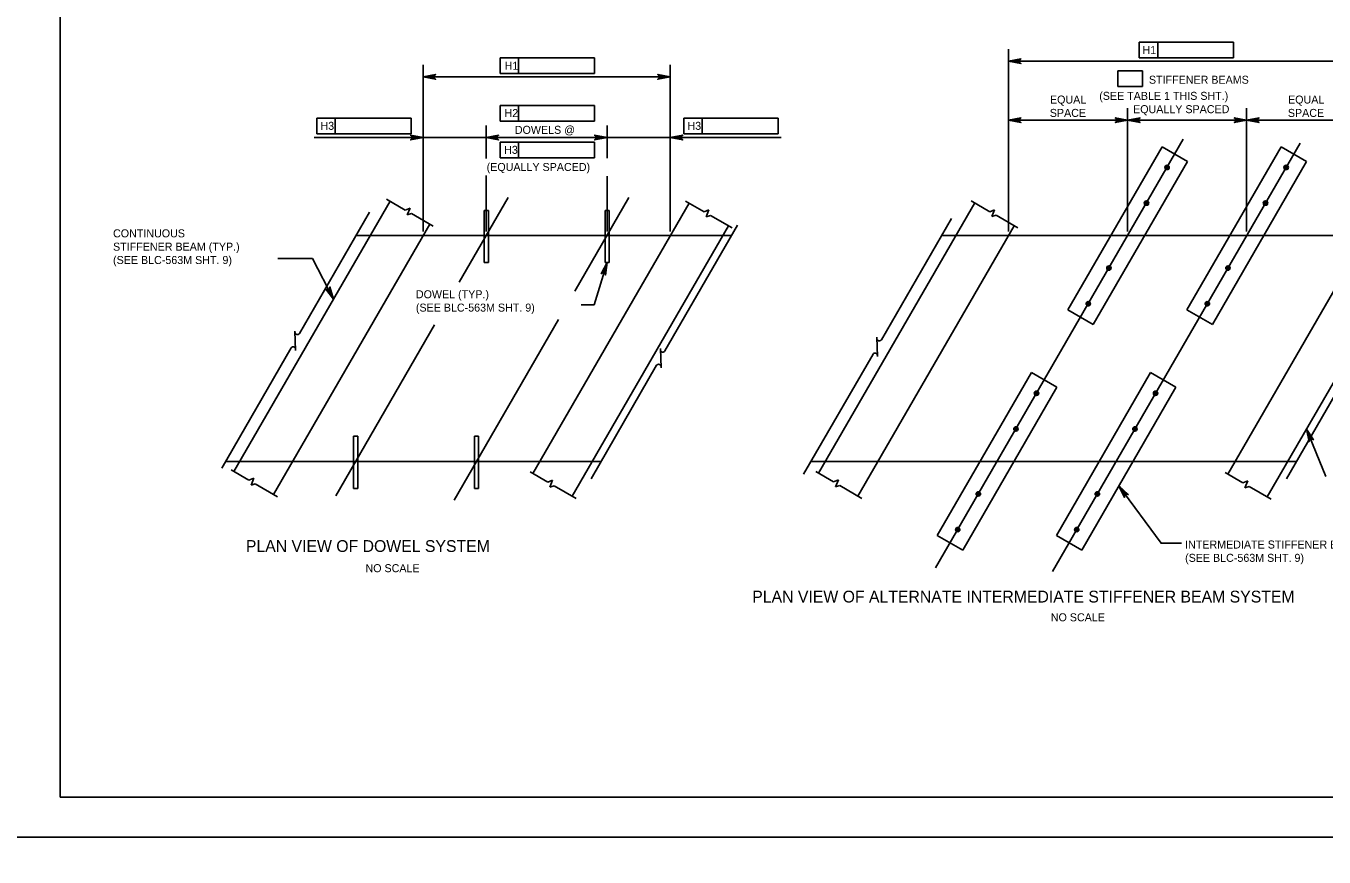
# Model space of a CAD drawing. Extents: x 638268 to 640277, y 295465 to 298435.
# Drawn here: x 639303.6 to 639790.3, y 297834 to 298145.6 of the extents above; entities that cross this region are included whole.
import ezdxf

# ---------------------------------------------------------------- set-up
doc = ezdxf.new("R2010")
doc.units = 0
for name, color, linetype in [('2', 7, 'Continuous'), ('3', 7, 'Continuous'), ('4', 7, 'Continuous'), ('PLT-BNDY', 7, 'Continuous')]:
    doc.layers.add(name, color=color, linetype=linetype)

# ---------------------------------------------------------------- blocks, each defined once
blk = doc.blocks.new('D')
at = {"layer": '3'}
for p, q in [((-0.48575, 0.574125), (-0.574125, 0.48575)), ((0.52325, -0.6115), (-0.574125, 0.48575)), ((0.6115, -0.52325), (-0.48575, 0.574125)), ((0.6115, -0.52325), (0.52325, -0.6115))]:
    blk.add_line(p, q, dxfattribs=at)

msp = doc.modelspace()

# ---------------------------------------------------------------- linework, layer by layer
at = {"layer": '2'}
for p, q in [((639316.46, 297856.46), (639316.46, 298420.46)), ((639427.37, 298067.04), (639568.2, 298067.04)), ((639646.92, 298067.04), (639828.98, 298067.04)), ((639378.41, 297982.34), (639519.24, 297982.34)), ((639597.96, 297982.34), (639780.02, 297982.34)), ((640102.46, 297856.46), (639316.46, 297856.46))]:
    msp.add_line(p, q, dxfattribs=at)
at = {"layer": '3'}
for p, q in [((639729.59, 298100.33), (639694.27, 298039.24)), ((639729.59, 298100.33), (639739.14, 298094.82)), ((639774.23, 298100.33), (639738.91, 298039.24)), ((639774.23, 298100.33), (639783.77, 298094.82)), ((639739.14, 298094.82), (639703.82, 298033.72)), ((639783.77, 298094.82), (639748.45, 298033.72)), ((639440.13, 298079.89), (639381.55, 297978.53)), ((639445.79, 298076.62), (639438.78, 298080.67)), ((639466.08, 298049.6), (639484.38, 298081.27)), ((639552.21, 298079.22), (639493.62, 297977.86)), ((639509.42, 298046.17), (639529.69, 298081.27)), ((639557.87, 298075.95), (639550.86, 298080)), ((639659.34, 298079.28), (639600.75, 297977.92)), ((639665, 298076), (639657.98, 298080.06)), ((639812.83, 298078.94), (639754.24, 297977.59)), ((639432.43, 298075.81), (639406.14, 298030.32)), ((639447.59, 298077.36), (639445.79, 298076.62)), ((639446.58, 298074.76), (639447.59, 298077.36)), ((639448.13, 298075.27), (639446.58, 298074.76)), ((639456.29, 298070.55), (639448.13, 298075.27)), ((639559.67, 298076.68), (639557.87, 298075.95)), ((639558.66, 298074.08), (639559.67, 298076.68)), ((639560.21, 298074.59), (639558.66, 298074.08)), ((639568.37, 298069.88), (639560.21, 298074.59)), ((639666.8, 298076.74), (639665, 298076)), ((639665.78, 298074.14), (639666.8, 298076.74)), ((639667.34, 298074.65), (639665.78, 298074.14)), ((639675.5, 298069.93), (639667.34, 298074.65)), ((639396.37, 297969.96), (639454.96, 298071.32)), ((639508.45, 297969.29), (639567.04, 298070.65)), ((639570.45, 298070.93), (639543.18, 298023.76)), ((639615.57, 297969.35), (639674.16, 298070.71)), ((639650.63, 298073.47), (639624.34, 298027.98)), ((639769.07, 297969.02), (639827.65, 298070.37)), ((639476.96, 298067.04), (639475.39, 298067.04)), ((639522.28, 298067.04), (639520.71, 298067.04)), ((639464.14, 297967.81), (639503.3, 298035.58)), ((639694.27, 298039.24), (639703.82, 298033.72)), ((639738.91, 298039.24), (639748.45, 298033.72)), ((639404.43, 298031.23), (639404.7, 298023.96)), ((639419.72, 297969.37), (639456.83, 298033.59)), ((639622.63, 298028.89), (639622.9, 298021.62)), ((639403.03, 298024.94), (639376.97, 297979.86)), ((639541.47, 298024.67), (639541.74, 298017.4)), ((639621.23, 298022.6), (639595.17, 297977.52)), ((639540.07, 298018.38), (639515.48, 297975.83)), ((639680.63, 298015.63), (639645.31, 297954.53)), ((639680.63, 298015.63), (639690.17, 298010.12)), ((639725.27, 298015.63), (639689.95, 297954.53)), ((639725.27, 298015.63), (639734.81, 298010.12)), ((639800.85, 298018.38), (639776.26, 297975.83)), ((639690.17, 298010.12), (639654.86, 297949.02)), ((639734.81, 298010.12), (639699.49, 297949.02)), ((639387.2, 297975.26), (639380.52, 297979.13)), ((639499.28, 297974.59), (639492.6, 297978.45)), ((639606.41, 297974.65), (639599.72, 297978.51)), ((639759.9, 297974.32), (639753.21, 297978.18)), ((639389, 297976), (639387.2, 297975.26)), ((639387.99, 297973.4), (639389, 297976)), ((639389.55, 297973.91), (639387.99, 297973.4)), ((639397.87, 297969.1), (639389.55, 297973.91)), ((639501.08, 297975.33), (639499.28, 297974.59)), ((639500.07, 297972.73), (639501.08, 297975.33)), ((639501.63, 297973.23), (639500.07, 297972.73)), ((639509.95, 297968.42), (639501.63, 297973.23)), ((639608.21, 297975.38), (639606.41, 297974.65)), ((639607.19, 297972.78), (639608.21, 297975.38)), ((639608.75, 297973.29), (639607.19, 297972.78)), ((639617.07, 297968.48), (639608.75, 297973.29)), ((639761.7, 297975.05), (639759.9, 297974.32)), ((639760.69, 297972.45), (639761.7, 297975.05)), ((639762.24, 297972.96), (639760.69, 297972.45)), ((639770.56, 297968.15), (639762.24, 297972.96)), ((639645.31, 297954.53), (639654.86, 297949.02)), ((639689.95, 297954.53), (639699.49, 297949.02))]:
    msp.add_line(p, q, dxfattribs=at)
for centre, radius in [((639731.48, 298092.59), 0.833), ((639731.48, 298092.59), 0.738), ((639731.48, 298092.59), 0.625), ((639776.12, 298092.59), 0.833), ((639776.12, 298092.59), 0.738), ((639776.12, 298092.59), 0.625), ((639731.48, 298092.59), 0.417), ((639731.48, 298092.59), 0.208), ((639776.12, 298092.59), 0.417), ((639776.12, 298092.59), 0.208), ((639723.75, 298079.21), 0.833), ((639723.75, 298079.21), 0.738), ((639723.75, 298079.21), 0.625), ((639723.75, 298079.21), 0.417), ((639723.75, 298079.21), 0.208), ((639768.38, 298079.21), 0.833), ((639768.38, 298079.21), 0.738), ((639768.38, 298079.21), 0.625), ((639768.38, 298079.21), 0.417), ((639768.38, 298079.21), 0.208), ((639709.66, 298054.84), 0.833), ((639709.66, 298054.84), 0.738), ((639709.66, 298054.84), 0.625), ((639709.66, 298054.84), 0.417), ((639709.66, 298054.84), 0.208), ((639754.3, 298054.84), 0.833), ((639754.3, 298054.84), 0.738), ((639754.3, 298054.84), 0.625), ((639754.3, 298054.84), 0.417), ((639754.3, 298054.84), 0.208), ((639701.93, 298041.47), 0.833), ((639701.93, 298041.47), 0.738), ((639701.93, 298041.47), 0.625), ((639701.93, 298041.47), 0.417), ((639701.93, 298041.47), 0.208), ((639746.56, 298041.47), 0.833), ((639746.56, 298041.47), 0.738), ((639746.56, 298041.47), 0.625), ((639746.56, 298041.47), 0.417), ((639746.56, 298041.47), 0.208), ((639682.52, 298007.89), 0.833), ((639682.52, 298007.89), 0.738), ((639682.52, 298007.89), 0.625), ((639682.52, 298007.89), 0.417), ((639682.52, 298007.89), 0.208), ((639727.16, 298007.89), 0.833), ((639727.16, 298007.89), 0.738), ((639727.16, 298007.89), 0.625), ((639727.16, 298007.89), 0.417), ((639727.16, 298007.89), 0.208), ((639674.79, 297994.51), 0.833), ((639674.79, 297994.51), 0.738), ((639674.79, 297994.51), 0.625), ((639674.79, 297994.51), 0.417), ((639674.79, 297994.51), 0.208), ((639719.42, 297994.51), 0.833), ((639719.42, 297994.51), 0.738), ((639719.42, 297994.51), 0.625), ((639719.42, 297994.51), 0.417), ((639719.42, 297994.51), 0.208), ((639660.7, 297970.14), 0.833), ((639660.7, 297970.14), 0.738), ((639660.7, 297970.14), 0.625), ((639660.7, 297970.14), 0.417), ((639660.7, 297970.14), 0.208), ((639705.34, 297970.14), 0.833), ((639705.34, 297970.14), 0.738), ((639705.34, 297970.14), 0.625), ((639705.34, 297970.14), 0.417), ((639705.34, 297970.14), 0.208), ((639652.97, 297956.76), 0.833), ((639652.97, 297956.76), 0.738), ((639652.97, 297956.76), 0.625), ((639652.97, 297956.76), 0.417), ((639652.97, 297956.76), 0.208), ((639697.6, 297956.76), 0.833), ((639697.6, 297956.76), 0.738), ((639697.6, 297956.76), 0.625), ((639697.6, 297956.76), 0.417), ((639697.6, 297956.76), 0.208)]:
    msp.add_circle(centre, radius, dxfattribs=at)
for centre, start, end in [((639405.36, 298030.78), 179.9708, 329.9708), ((639403.77, 298024.42), 2.1036, 144.6422), ((639623.55, 298028.44), 179.9708, 329.9708), ((639542.4, 298024.22), 179.9708, 329.9708), ((639621.97, 298022.08), 2.1036, 144.6422), ((639540.82, 298017.86), 2.1036, 144.6422)]:
    msp.add_arc(centre, 0.909, start, end, dxfattribs=at)
at = {"layer": '4'}
for p, q in [((639721.06, 298139.63), (639721.06, 298133.73)), ((639721.06, 298139.63), (639756.36, 298139.63)), ((639727.95, 298139.63), (639727.95, 298133.73)), ((639756.36, 298139.63), (639756.36, 298133.73)), ((639481.44, 298133.75), (639516.74, 298133.75)), ((639481.44, 298133.75), (639481.44, 298127.84)), ((639488.33, 298133.75), (639488.33, 298127.84)), ((639516.74, 298133.75), (639516.74, 298127.84)), ((639672.04, 298068.61), (639672.04, 298136.91)), ((639805.95, 298132.41), (639672.04, 298132.41)), ((639756.36, 298133.73), (639721.06, 298133.73)), ((639452.48, 298070.17), (639452.48, 298131.02)), ((639516.74, 298127.84), (639481.44, 298127.84)), ((639545.17, 298070.17), (639545.17, 298131.02)), ((639712.97, 298128.8), (639722.25, 298128.8)), ((639712.97, 298128.8), (639712.97, 298122.89)), ((639722.25, 298128.8), (639722.25, 298122.89)), ((639545.17, 298126.52), (639452.48, 298126.52)), ((639722.25, 298122.89), (639712.97, 298122.89)), ((639481.44, 298115.88), (639481.44, 298109.97)), ((639481.44, 298115.88), (639516.74, 298115.88)), ((639488.33, 298115.88), (639488.33, 298109.97)), ((639516.74, 298115.88), (639516.74, 298109.97)), ((639672.04, 298068.61), (639672.04, 298114.76)), ((639716.68, 298068.61), (639716.68, 298114.76)), ((639761.31, 298068.61), (639761.31, 298114.76)), ((639412.67, 298111.08), (639447.97, 298111.08)), ((639412.67, 298111.08), (639412.67, 298105.18)), ((639419.56, 298111.08), (639419.56, 298105.18)), ((639447.97, 298111.08), (639447.97, 298105.18)), ((639452.48, 298068.61), (639452.48, 298108.32)), ((639476.16, 298095.9), (639476.16, 298108.32)), ((639516.74, 298109.97), (639481.44, 298109.97)), ((639521.48, 298096.09), (639521.48, 298108.32)), ((639545.17, 298068.61), (639545.17, 298108.32)), ((639550.3, 298111.08), (639585.6, 298111.08)), ((639550.3, 298111.08), (639550.3, 298105.18)), ((639557.19, 298111.08), (639557.19, 298105.18)), ((639585.6, 298111.08), (639585.6, 298105.18)), ((639713.68, 298110.26), (639672.04, 298110.26)), ((639758.31, 298110.26), (639719.68, 298110.26)), ((639764.31, 298110.26), (639805.95, 298110.26)), ((639449.48, 298103.82), (639411.6, 298103.82)), ((639447.97, 298105.18), (639412.67, 298105.18)), ((639476.16, 298103.82), (639452.46, 298103.82)), ((639518.47, 298103.82), (639479.16, 298103.82)), ((639518.47, 298103.82), (639515.47, 298103.82)), ((639545.17, 298103.82), (639521.47, 298103.82)), ((639548.17, 298103.82), (639586.76, 298103.82)), ((639585.6, 298105.18), (639550.3, 298105.18)), ((639737.54, 298103.13), (639644.64, 297942.41)), ((639481.44, 298102.09), (639516.74, 298102.09)), ((639481.44, 298102.09), (639481.44, 298096.19)), ((639488.33, 298102.09), (639488.33, 298096.19)), ((639516.74, 298102.09), (639516.74, 298096.19)), ((639781.36, 298101.73), (639688.46, 297941.01)), ((639516.74, 298096.19), (639481.44, 298096.19)), ((639476.16, 298068.61), (639476.16, 298089.57)), ((639521.48, 298068.61), (639521.48, 298089.27)), ((639411.07, 298058.42), (639397.98, 298058.42)), ((639516.63, 298041.04), (639511.77, 298041.04)), ((639729.1, 297951.66), (639736.94, 297951.66))]:
    msp.add_line(p, q, dxfattribs=at)
for points in [[(639672.04, 298132.41), (639676.7, 298133.28), (639676.35, 298133.03), (639676.16, 298132.72), (639676.11, 298132.41), (639676.16, 298132.09), (639676.35, 298131.78), (639676.7, 298131.53), (639672.04, 298132.41), (639676.35, 298131.78), (639676.16, 298132.09), (639672.04, 298132.41), (639676.11, 298132.41), (639676.16, 298132.72), (639672.04, 298132.41), (639676.35, 298133.03)], [(639452.48, 298126.52), (639457.15, 298127.39), (639456.79, 298127.15), (639456.6, 298126.83), (639456.55, 298126.52), (639456.6, 298126.21), (639456.79, 298125.9), (639457.15, 298125.65), (639452.48, 298126.52), (639456.79, 298125.9), (639456.6, 298126.21), (639452.48, 298126.52), (639456.55, 298126.52), (639456.6, 298126.83), (639452.48, 298126.52), (639456.79, 298127.15)], [(639545.17, 298126.52), (639540.51, 298125.65), (639540.87, 298125.9), (639541.06, 298126.21), (639541.11, 298126.52), (639541.06, 298126.83), (639540.87, 298127.15), (639540.51, 298127.39), (639545.17, 298126.52), (639540.87, 298127.15), (639541.06, 298126.83), (639545.17, 298126.52), (639541.11, 298126.52), (639541.06, 298126.21), (639545.17, 298126.52), (639540.87, 298125.9)], [(639672.04, 298110.26), (639676.7, 298111.13), (639676.35, 298110.88), (639676.16, 298110.57), (639676.11, 298110.26), (639676.16, 298109.94), (639676.35, 298109.63), (639676.7, 298109.38), (639672.04, 298110.26), (639676.35, 298109.63), (639676.16, 298109.94), (639672.04, 298110.26), (639676.11, 298110.26), (639676.16, 298110.57), (639672.04, 298110.26), (639676.35, 298110.88)], [(639716.68, 298110.26), (639712.02, 298109.38), (639712.38, 298109.63), (639712.56, 298109.94), (639712.62, 298110.26), (639712.56, 298110.57), (639712.38, 298110.88), (639712.02, 298111.13), (639716.68, 298110.26), (639712.38, 298110.88), (639712.56, 298110.57), (639716.68, 298110.26), (639712.62, 298110.26), (639712.56, 298109.94), (639716.68, 298110.26), (639712.38, 298109.63)], [(639716.68, 298110.26), (639721.34, 298109.38), (639720.98, 298109.63), (639720.8, 298109.94), (639720.74, 298110.26), (639720.8, 298110.57), (639720.98, 298110.88), (639721.34, 298111.13), (639716.68, 298110.26), (639720.98, 298110.88), (639720.8, 298110.57), (639716.68, 298110.26), (639720.74, 298110.26), (639720.8, 298109.94), (639716.68, 298110.26), (639720.98, 298109.63)], [(639761.31, 298110.26), (639756.65, 298109.38), (639757.01, 298109.63), (639757.2, 298109.94), (639757.25, 298110.26), (639757.2, 298110.57), (639757.01, 298110.88), (639756.65, 298111.13), (639761.31, 298110.26), (639757.01, 298110.88), (639757.2, 298110.57), (639761.31, 298110.26), (639757.25, 298110.26), (639757.2, 298109.94), (639761.31, 298110.26), (639757.01, 298109.63)], [(639761.31, 298110.26), (639765.98, 298109.38), (639765.62, 298109.63), (639765.43, 298109.94), (639765.38, 298110.26), (639765.43, 298110.57), (639765.62, 298110.88), (639765.98, 298111.13), (639761.31, 298110.26), (639765.62, 298110.88), (639765.43, 298110.57), (639761.31, 298110.26), (639765.38, 298110.26), (639765.43, 298109.94), (639761.31, 298110.26), (639765.62, 298109.63)], [(639452.48, 298103.82), (639447.82, 298102.94), (639448.18, 298103.19), (639448.37, 298103.5), (639448.42, 298103.82), (639448.37, 298104.13), (639448.18, 298104.44), (639447.82, 298104.69), (639452.48, 298103.82), (639448.18, 298104.44), (639448.37, 298104.13), (639452.48, 298103.82), (639448.42, 298103.82), (639448.37, 298103.5), (639452.48, 298103.82), (639448.18, 298103.19)], [(639476.16, 298103.82), (639480.82, 298104.69), (639480.46, 298104.44), (639480.27, 298104.13), (639480.22, 298103.82), (639480.27, 298103.5), (639480.46, 298103.19), (639480.82, 298102.94), (639476.16, 298103.82), (639480.46, 298103.19), (639480.27, 298103.5), (639476.16, 298103.82), (639480.22, 298103.82), (639480.27, 298104.13), (639476.16, 298103.82), (639480.46, 298104.44)], [(639521.47, 298103.82), (639516.81, 298102.94), (639517.17, 298103.19), (639517.36, 298103.5), (639517.41, 298103.82), (639517.36, 298104.13), (639517.17, 298104.44), (639516.81, 298104.69), (639521.47, 298103.82), (639517.17, 298104.44), (639517.36, 298104.13), (639521.47, 298103.82), (639517.41, 298103.82), (639517.36, 298103.5), (639521.47, 298103.82), (639517.17, 298103.19)], [(639545.17, 298103.82), (639549.84, 298104.69), (639549.48, 298104.44), (639549.29, 298104.13), (639549.24, 298103.82), (639549.29, 298103.5), (639549.48, 298103.19), (639549.84, 298102.94), (639545.17, 298103.82), (639549.48, 298103.19), (639549.29, 298103.5), (639545.17, 298103.82), (639549.24, 298103.82), (639549.29, 298104.13), (639545.17, 298103.82), (639549.48, 298104.44)], [(639418.95, 298043.24), (639411.07, 298058.42)], [(639521.48, 298056.93), (639516.62, 298041.03)], [(639521.48, 298056.93), (639520.95, 298052.22), (639520.82, 298052.64), (639520.58, 298052.91), (639520.29, 298053.05), (639519.98, 298053.09), (639519.62, 298053), (639519.28, 298052.73), (639521.48, 298056.93), (639519.62, 298053), (639519.98, 298053.09), (639521.48, 298056.93), (639520.29, 298053.05), (639520.58, 298052.91), (639521.48, 298056.93), (639520.82, 298052.64)], [(639418.95, 298043.24), (639416.02, 298046.97), (639416.41, 298046.77), (639416.77, 298046.75), (639417.08, 298046.85), (639417.33, 298047.04), (639417.52, 298047.35), (639417.58, 298047.78), (639418.95, 298043.24), (639417.52, 298047.35), (639417.33, 298047.04), (639418.95, 298043.24), (639417.08, 298046.85), (639416.77, 298046.75), (639418.95, 298043.24), (639416.41, 298046.77)], [(639783.76, 297994.44), (639790.99, 297976.71)], [(639783.76, 297994.44), (639786.33, 297990.45), (639785.96, 297990.69), (639785.6, 297990.74), (639785.3, 297990.67), (639785.03, 297990.51), (639784.81, 297990.22), (639784.71, 297989.79), (639783.76, 297994.44), (639784.81, 297990.22), (639785.03, 297990.51), (639783.76, 297994.44), (639785.3, 297990.67), (639785.6, 297990.74), (639783.76, 297994.44), (639785.96, 297990.69)], [(639713.43, 297973.12), (639729.2, 297951.63)], [(639713.43, 297973.12), (639716.89, 297969.88), (639716.47, 297970.02), (639716.11, 297969.99), (639715.83, 297969.85), (639715.61, 297969.62), (639715.47, 297969.28), (639715.48, 297968.85), (639713.43, 297973.12), (639715.47, 297969.28), (639715.61, 297969.62), (639713.43, 297973.12), (639715.83, 297969.85), (639716.11, 297969.99), (639713.43, 297973.12), (639716.47, 297970.02)]]:
    msp.add_lwpolyline(points, dxfattribs=at)
for points in [[(639675.04, 298132.91), (639675.04, 298131.91), (639672.04, 298132.41)], [(639455.48, 298127.02), (639455.48, 298126.02), (639452.48, 298126.52)], [(639542.17, 298127.02), (639542.17, 298126.02), (639545.17, 298126.52)], [(639675.04, 298110.76), (639675.04, 298109.76), (639672.04, 298110.26)], [(639713.68, 298110.76), (639713.68, 298109.76), (639716.68, 298110.26)], [(639719.68, 298110.76), (639719.68, 298109.76), (639716.68, 298110.26)], [(639758.31, 298110.76), (639758.31, 298109.76), (639761.31, 298110.26)], [(639764.31, 298110.76), (639764.31, 298109.76), (639761.31, 298110.26)], [(639449.48, 298104.32), (639449.48, 298103.32), (639452.48, 298103.82)], [(639479.16, 298104.32), (639479.16, 298103.32), (639476.16, 298103.82)], [(639518.47, 298104.32), (639518.47, 298103.32), (639521.47, 298103.82)], [(639548.17, 298104.32), (639548.17, 298103.32), (639545.17, 298103.82)], [(639521.48, 298056.93), (639520.36, 298054.14), (639520.84, 298053.99)], [(639418.95, 298043.24), (639417.79, 298046.02), (639417.34, 298045.79)], [(639783.76, 297994.44), (639784.66, 297991.57), (639785.13, 297991.75)], [(639713.43, 297973.12), (639715, 297970.56), (639715.4, 297970.85)]]:
    msp.add_lwpolyline(points, close=True, dxfattribs=at)
at = {"layer": 'PLT-BNDY'}
for points in [[(639276.46, 298435.46), (640117.46, 298435.46), (640117.46, 297841.46), (639276.46, 297841.46)], [(639276.46, 297841.46), (640117.46, 297841.46), (640117.46, 297247.46), (639276.46, 297247.46)]]:
    msp.add_lwpolyline(points, close=True, dxfattribs=at)

# ---------------------------------------------------------------- block references
at = {"layer": '4', "xscale": 12.59905511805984, "yscale": -12.599055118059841, "rotation": -135.00004849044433}
for p in [(639476.18, 298067.04), (639521.5, 298067.04), (639427.22, 297982.34), (639472.54, 297982.34)]:
    msp.add_blockref('D', p, dxfattribs=at)

# ---------------------------------------------------------------- texts
at = {"layer": '4'}
for s, height, p in [('H1', 3, (639722.24, 298135.09)), ('H1', 3, (639483.07, 298129.21)), ('STIFFENER BEAMS', 3, (639724.67, 298123.98)), ('EQUAL', 3, (639687.57, 298116.54)), ('(SEE TABLE 1 THIS SHT.)', 3, (639706.04, 298117.94)), ('EQUAL', 3, (639776.84, 298116.54)), ('H2', 3, (639483.03, 298111.47)), ('SPACE', 3, (639687.5, 298111.54)), ('EQUALLY SPACED', 3, (639718.73, 298112.94)), ('SPACE', 3, (639776.77, 298111.54)), ('H3', 3, (639414, 298106.69)), ('DOWELS @', 3, (639486.9, 298105.19)), ('H3', 3, (639551.63, 298106.69)), ('H3', 3, (639482.89, 298097.69)), ('(EQUALLY SPACED)', 3, (639476.33, 298091.26)), ('CONTINUOUS', 3, (639336.23, 298066.37)), ('STIFFENER BEAM (TYP.)', 3, (639336.23, 298061.37)), ('(SEE BLC-563M SHT. 9)', 3, (639336.23, 298056.37)), ('DOWEL (TYP.)', 3, (639449.79, 298043.52)), ('(SEE BLC-563M SHT. 9)', 3, (639449.79, 298038.52)), ('PLAN VIEW OF DOWEL SYSTEM', 4.4292, (639386.04, 297948.38)), ('INTERMEDIATE STIFFENER BEAM (TYP.)', 3, (639738.23, 297949.67)), ('(SEE BLC-563M SHT. 9)', 3, (639738.23, 297944.67)), ('NO SCALE', 3, (639430.89, 297940.79)), ('PLAN VIEW OF ALTERNATE INTERMEDIATE STIFFENER BEAM SYSTEM', 4.4292, (639575.92, 297929.42)), ('NO SCALE', 3, (639687.88, 297922.37))]:
    msp.add_text(s, height=height, dxfattribs=at).set_placement(p)

doc.saveas('drawing.dxf')
